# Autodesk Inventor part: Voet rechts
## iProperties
Created: 2007-06
Part Number: Voet rechts
Material: Steel
Document SubType Name: Modeling
Designer: Phil Trethewie
Author: Phil Trethewie
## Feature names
1. Sweep1
